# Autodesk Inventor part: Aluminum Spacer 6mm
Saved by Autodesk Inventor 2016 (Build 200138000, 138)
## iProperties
Created: 2015-11
Part Number: Aluminum Spacer 6mm
Material: Generic
Document SubType Name: Modeling
Designer: John
Density: 1 g/cm^3
Appearance: Default
Author: John
Revision Number: ANY
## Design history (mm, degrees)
chamfer "Chamfer1"
body "Solid1"
